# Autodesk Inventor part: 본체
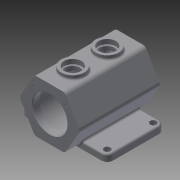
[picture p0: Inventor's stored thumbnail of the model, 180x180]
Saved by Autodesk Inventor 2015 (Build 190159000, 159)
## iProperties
Created: 2021-06
Part Number: 본체
Material: 일반
Document SubType Name: Modeling
Designer: now
Density: 1 g/cm^3
Appearance: 기본값
Mass: 557.621 g
Surface Area: 1096.1 cm^2
Volume: 557.621 cm^3
Author: now
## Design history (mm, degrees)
sketch "스케치6" dims "d57" = 105
  geometry: L1 (-52.5, 0)-(-26.25, 45.466); L2 (-26.25, 45.466)-(26.25, 45.466); L3 (26.25, 45.466)-(52.5, 0); L4 (52.5, 0)-(26.25, -45.466); L5 (26.25, -45.466)-(-26.25, -45.466); L6 (-26.25, -45.466)-(-52.5, 0); 3 further points
  constraints: 12 end point, 2 coincident, 1 horizontal, 1 horizontal alignment, 15 other
extrude "돌출3" new body sketch "스케치6" stored distance "d20" = 140; taper "d21" = 0 deg
node "작업 평면7"
sketch "스케치11"
  geometry: L1 (-75, -45)-(75, -45); L2 (75, -45)-(75, 55); L3 (75, 55)-(-75, 55); L4 (-75, 55)-(-75, -45); L5 (-26.25, -70)-(26.25, -70) reference; 3 further points
  constraints: 8 end point, 2 midpoint, 2 parallel, 1 horizontal, 1 perpendicular, 1 vertical alignment
  dimensions: "d41" = 100 distance of L3.end L1.start; "d42" = 150 distance of L2.end L3.end; "d43" = 25 distance between parallel lines of L1 L5
extrude "돌출5" join sketch "스케치11" distance "d44" = 12; taper "d45" = 0 deg
node "작업 평면8"
sketch "스케치13"
  geometry: L1 (26.25, -70)-(-26.25, -70) reference; C1 r 20 at (0, -30); C2 r 20 at (0, 30); 1 further point
  constraints: 2 centre point
  dimensions: "d48" = 20 radius of C1; "d49" = 20 radius of C2; "d52" = 40 distance from line of C1.centre L1; "d53" = 60 distance of C2.centre C1.centre
extrude "돌출6" join sketch "스케치13" stored distance "d54" = 12; taper "d55" = 0 deg
sketch "스케치14"
  geometry: C1 r 30 at (0, 0); 1 further point
  constraints: 1 centre point, 1 coincident
  dimensions: "d56" = 30 radius of C1
extrude "돌출7" cut sketch "스케치14" distance "d58" = 12; taper "d59" = 0 deg
sketch "스케치15"
  geometry: C1 r 30 at (0, 0) reference; C2 r 37.5 at (0, 0)
  constraints: 1 centre point, 1 coincident
  dimensions: "d60" = 37.5 radius of C2
extrude "돌출8" cut sketch "스케치15" distance "d61" = 116; taper "d62" = 0 deg
sketch "스케치16"
  geometry: C1 r 30 at (0, 0); 1 further point
  constraints: 1 centre point, 1 coincident
  dimensions: "d63" = 30 radius of C1
extrude "돌출9" cut sketch "스케치16" distance "d64" = 12; taper "d65" = 0 deg
fillet "모깎기1" dims "d66" = 10
hole "구멍1" diameter "d69" = 11; stored, may be unused: countersink angle "d73" = 90 deg, drill point angle "d75" = 118 deg; dims "d67" = 10, "d68" = 10, "d70" = 6, "d71" = 4, "d72" = 2, "d74" = 8
hole "구멍2" diameter "d78" = 11; stored, may be unused: countersink angle "d82" = 90 deg, drill point angle "d84" = 118 deg; dims "d76" = 10, "d77" = 10, "d79" = 6, "d80" = 4, "d81" = 2, "d83" = 8
hole "구멍3" diameter "d87" = 11; stored, may be unused: countersink angle "d91" = 90 deg, drill point angle "d93" = 118 deg; dims "d85" = 10, "d86" = 10, "d88" = 6, "d89" = 4, "d90" = 2, "d92" = 8
hole "구멍4" diameter "d96" = 11; stored, may be unused: countersink angle "d100" = 90 deg, drill point angle "d102" = 118 deg; dims "d94" = 10, "d95" = 10, "d97" = 6, "d98" = 4, "d99" = 2, "d101" = 8
hole "구멍5" diameter "d106" = 25; stored, may be unused: countersink angle "d110" = 90 deg, drill point angle "d112" = 118 deg; dims "d104" = 10, "d105" = 10, "d107" = 6, "d108" = 30, "d109" = 8, "d111" = 20
hole "구멍6" diameter "d115" = 25; stored, may be unused: countersink angle "d119" = 90 deg, drill point angle "d121" = 118 deg; dims "d113" = 10, "d114" = 10, "d116" = 6, "d117" = 30, "d118" = 8, "d120" = 20
fillet "모깎기2" dims "d133" = 8
fillet "모깎기4" dims "d135" = 8
fillet "모깎기5" dims "d136" = 3
fillet "모깎기6" dims "d137" = 3
fillet "모깎기7" dims "d138" = 3
chamfer "모따기1" distance "d139" = 1; stored, may be unused: second distance "d140" = 2, angle "d141" = 45 deg
sketch "스케치19"
  geometry: L1 (-75, 45)-(-75, -35) reference; L2 (-44.417, 55)-(-65, 55) reference; L3 (-65, -45)-(-44.417, -45) reference; 2 further points
  constraints: 1 other
  dimensions: "d142" = 14 distance from line of point (-61, 5) L1; "d176" = 50 distance from line of point (-61, 5) L3
feature "엠보싱1" sketch "스케치19" dims "d57" = 105, "d58" = 12, "d144" = 0.5, "d145" = 0, "d169" = 8
fillet "모깎기8" dims "d146" = 3
chamfer "모따기2" distance "d147" = 1; stored, may be unused: second distance "d148" = 2, angle "d149" = 45 deg
sketch "스케치21" dims "d152" = 40
  geometry: L1 (0, 0)-(-28.284, 28.284); L2 (0, 0)-(0, 25); C1 r 31 at (0, 0) reference; 1 further point
  constraints: 4 end point, 2 coincident, 1 vertical, 3 other
  dimensions: "d153" = 45 deg angle of L2 L1
hole "구멍8" sketch "스케치21" at (-28.284, 28.284) diameter "d154" = 3.242; stored, may be unused: countersink angle "d158" = 90 deg, drill point angle "d160" = 118 deg; dims "d155" = 8, "d156" = 30, "d157" = 8, "d159" = 10
fillet "모깎기9" dims "d164" = 5
sketch "스케치22" dims "d165" = 40
  geometry: C1 r 31 at (0, 0) reference; 2 further points
  constraints: 1 coincident, 1 vertical alignment, 2 other
hole "구멍9" sketch "스케치22" at (0, -40) diameter "d166" = 3.242; stored, may be unused: countersink angle "d170" = 90 deg, drill point angle "d172" = 118 deg; dims "d167" = 8, "d168" = 30, "d169" = 8, "d171" = 10
node "솔리드2"
pattern_circular "원형 패턴2" dims angle "d162" = 360 deg
pattern_circular "원형 패턴3" dims angle "d174" = 360 deg
other parameters: "d47" = 52.5
